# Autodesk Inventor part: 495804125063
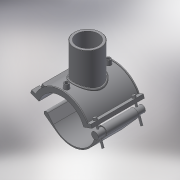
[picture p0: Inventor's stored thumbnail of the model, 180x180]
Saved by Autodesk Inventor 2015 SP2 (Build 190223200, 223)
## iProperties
Created: 2017-07
Part Number: 495804125063
Material: Generic
Description: PLASSON BRANCH SADDLE 125-63
Document SubType Name: Modeling
Designer: KIM
Density: 1 g/cm^3
Appearance: Default
Author: KIM
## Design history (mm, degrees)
derived "495804.ipt"
feature "Solid1::495804.ipt"
feature "Solid2::495804.ipt"
tag "TaggingFeature1"
body "Solid1"
body "Solid2"
other parameters: "d0" = 125, "d2" = 162, "d3" = 31.25, "d4" = 118, "d5" = 0, "d6" = 0.1, "d8" = 0, "d19" = 6, "d20" = 6, "d21" = 70.8, "d23" = 0, "d24" = 35.4, "d26" = 0, "d27" = 3, "d28" = 3, "d29" = 3, "d30" = 41.66667, "d31" = 6, "d32" = 0, "d33" = 0, "d34" = 0.6, "d40" = 74.36, "d41" = 69.3, "d43" = 0, "d45" = 0, "d47" = 165.5, "d48" = 63, "d50" = 0, "d70" = 15, "d72" = 0, "d73" = 6, "d75" = 5, "d76" = 0, "d77" = 6.25, "d78" = 92.5, "d79" = 15, "d80" = 47.2, "d82" = 5 deg, "d84" = 4, "d85" = 14, "d86" = 0, "d87" = 3, "d88" = 0, "d89" = 1, "d90" = 1, "d91" = 94.4, "d92" = 0, "d93" = 0.5, "d94" = 65.78947, "d96" = 145.86, "d97" = 2.36, "d98" = 0, "d102" = 1.89, "d103" = 50.4, "d105" = 0, "d109" = -31.33333, "d117" = 0.63, "d120" = 140 deg, "d121" = 24.228, "d122" = 20 deg, "d123" = 286, "d124" = 85.8, "d126" = 0, "d143" = 131.25, "d150" = 22.5, "d159" = 3.6, "d161" = 3.125, "d162" = 70.8, "d163" = 0, "d167" = 25, "d168" = 65, "d173" = 1, "d175" = 62.5, "d176" = 20 deg, "d177" = 8.75, "d178" = 18, "d180" = 0, "d185" = 38.35, "d186" = 38.35, "d187" = 71.5, "d188" = 5.4, "d189" = 8.75, "d190" = 0, "d191" = 107.25, "d200" = 9, "d202" = 0, "d216" = 106.2, "d217" = 0, "d221" = 43.66, "d222" = 8.75, "d223" = 5.25, "d224" = 62.5, "d225" = 5.25, "d227" = 18, "d230" = 77.5, "d236" = 20 deg, "d237" = 78.5, "d238" = 20 deg, "d239" = 8.75, "d_" = 125, "B_" = 162, "H_" = 94, "L_" = 118, "d_t" = 6, "d_1" = 63, "H_1" = 85, "d1" = 143, "d148" = 3.125, "d160" = 3.125
